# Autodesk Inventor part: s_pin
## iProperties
Author: GJOHNST2
Shininess: 20.0
Length Units: 11272
Angle Units: 11286
Time Units: 11279
Mass Units: 11290
Length Display Precision: 3
Angle Display Precision: 2
Compacted: True
PropertySet Name: _Private Model Information
Created: 2001-12
Part Number: s_pin
Document SubType Name: Modeling
Designer: GJOHNST2
Control State: 0
Master: False
Checked Out: False
PropertySet Name: Design Tracking Control
Density: 0.0
Volumn: 0.0
Area: 0.0
PropertySet Name: Model Information
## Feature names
1. Extrusion1
2. Extrusion2
3. Fillet1
4. Extrusion3
5. Fillet2
